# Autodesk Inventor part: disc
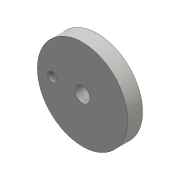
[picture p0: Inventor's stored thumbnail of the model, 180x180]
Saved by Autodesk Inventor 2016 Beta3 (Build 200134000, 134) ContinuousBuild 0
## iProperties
Created: 2016-03
Part Number: disc
Material: Generic
Document SubType Name: Modeling
Designer: Gaurav
Density: 1 g/cm^3
Appearance: Default
Author: Gaurav
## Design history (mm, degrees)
sketch "Sketch1"
  geometry: C1 r 15 at (0, 0); C2 r 2.5 at (0, 0); C3 r 1.5 at (10, 0); 1 further point
  constraints: 3 centre point, 2 coincident
  dimensions: "d0" = 30 diameter of C1; "d1" = 5 diameter of C2; "d2" = 3 diameter of C3; "d3" = 10 distance of point (0, 0) C3.centre
extrude "Extrusion1" new body sketch "Sketch1" distance "d4" = 5; taper "d5" = 0 deg
body "Solid1"
